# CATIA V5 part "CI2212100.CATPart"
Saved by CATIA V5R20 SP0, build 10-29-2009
Part number: CI2212100
Bounding box of the stored display mesh (mm): x -12 to 12, y -9.46 to 118, z -16.675 to 13.021
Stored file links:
  C:\Users\Raffaele\Desktop\3D X SITO CF\BOLEX\19-INCLINED ASSEMBLY REF_CI\CI2212100.CATPart
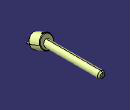
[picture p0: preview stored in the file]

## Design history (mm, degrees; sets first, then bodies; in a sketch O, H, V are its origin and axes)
Set1
  DatumSurface1 to DatumSurface16 "MANIFOLD_SOLID_BREP #380"
  DatumSurface17 to DatumSurface39 "MANIFOLD_SOLID_BREP #1130"
Body1 (main body)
